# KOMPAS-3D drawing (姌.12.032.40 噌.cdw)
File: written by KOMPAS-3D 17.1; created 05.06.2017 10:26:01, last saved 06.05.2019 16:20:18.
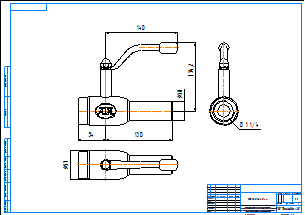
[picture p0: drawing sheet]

Sheet 1: A2, landscape

Title block, sheet 1: name: КШ.12.032.40 рс; material: Внимание! Данный продукт является объектом авторского права ООО «Торговый Дом АДЛ». / Запрещается изменение, копирование, распространение / (в том числе путем копирования на другие сайты и ресурсы в Интернете) / или любое иное использование информации и объектов без предварительного / согласия правообладателя (ООО «Торговый Дом АДЛ»).; sheets: 1; organisation: ООО "Торговый дом АДЛ"; sheet format: A2; stored path: C:\Users\kka\KOMPAS_Work\Модели кранов для исследований\Все краники\Редуцированный резьба-сварка ШК БИВАЛ\КШ.02.015.40 рс.cdw

Views: Вид 1, Проекционный вид 2, Проекционный вид 3
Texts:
  Klimkovich
  ADL
Dimensions and other numbers on the sheet: 140; 38; 130; 54; 134,2; 57; 1:1; 1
